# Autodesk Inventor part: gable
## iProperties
Created: 2005-05
Part Number: gable
Material: cherry
Document SubType Name: Modeling
Designer: a.campbell
Manufacturer: Standard
Standards Organization: Custom
length: 464
thickness: 19
width: 423
Author: a.campbell
Comments: machine to detail
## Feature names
1. Extrusion1
2. Extrusion2
